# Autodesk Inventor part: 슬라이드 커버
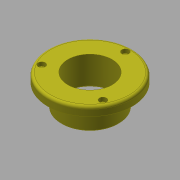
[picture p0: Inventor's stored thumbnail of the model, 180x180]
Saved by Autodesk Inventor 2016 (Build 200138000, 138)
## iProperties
Created: 2015-10
Part Number: 슬라이드 커버
Document SubType Name: Modeling
Designer: mdu
Density: 7.86 g/cm^3
Material: 강철, 연강
Mass: 635.45 g
Surface Area: 238.05 cm^2
Volume: 80.8461 cm^3
Appearance: 밝은 황색
Author: mdu
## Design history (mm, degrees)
sketch "스케치1"
  geometry: C1 r 47.5 at (0, 0); C2 r 32.5 at (0, 0); 1 further point
  constraints: 2 centre point, 2 coincident
  dimensions: "d33" = 95 diameter of C1; "d35" = 65 diameter of C2
extrude "돌출1" new body sketch "스케치1" distance "d0" = 10; taper "d1" = 0 deg
extrude "돌출2" join sketch "스케치1" distance "d2" = 25; taper "d3" = 0 deg
hole "구멍1" diameter "d6" = 50; stored, may be unused: countersink angle "d10" = 90 deg, drill point angle "d12" = 118 deg; dims "d4" = 10, "d5" = 10, "d7" = 6, "d8" = 4, "d9" = 2, "d11" = 8
sketch "스케치2" dims "d36" = 80
  geometry: 4 further points
  constraints: 2 coincident, 2 vertical alignment, 2 other
hole "구멍2" sketch "스케치2" at (0, 40) diameter "d13" = 4.5; stored, may be unused: countersink angle "d17" = 90 deg, drill point angle "d19" = 118 deg; dims "d14" = 6, "d15" = 8, "d16" = 4.4, "d18" = 8
fillet "모깎기1" dims "d23" = 3
chamfer "모따기1" distance "d24" = 1; stored, may be unused: second distance "d25" = 2, angle "d26" = 45 deg
sketch "스케치3"
  geometry: C1 r 25 at (0, 0); C2 r 30 at (0, 0); C3 r 26 at (0, 0) reference; 1 further point
  constraints: 2 centre point, 2 coincident
  dimensions: "d27" = 60 diameter of C2
extrude "돌출3" cut sketch "스케치3" distance "d28" = 3; taper "d29" = 0 deg
chamfer "모따기2" distance "d30" = 1; stored, may be unused: second distance "d31" = 2, angle "d32" = 45 deg
node "솔리드1"
pattern_circular "원형 패턴1" dims angle "d21" = 360 deg
